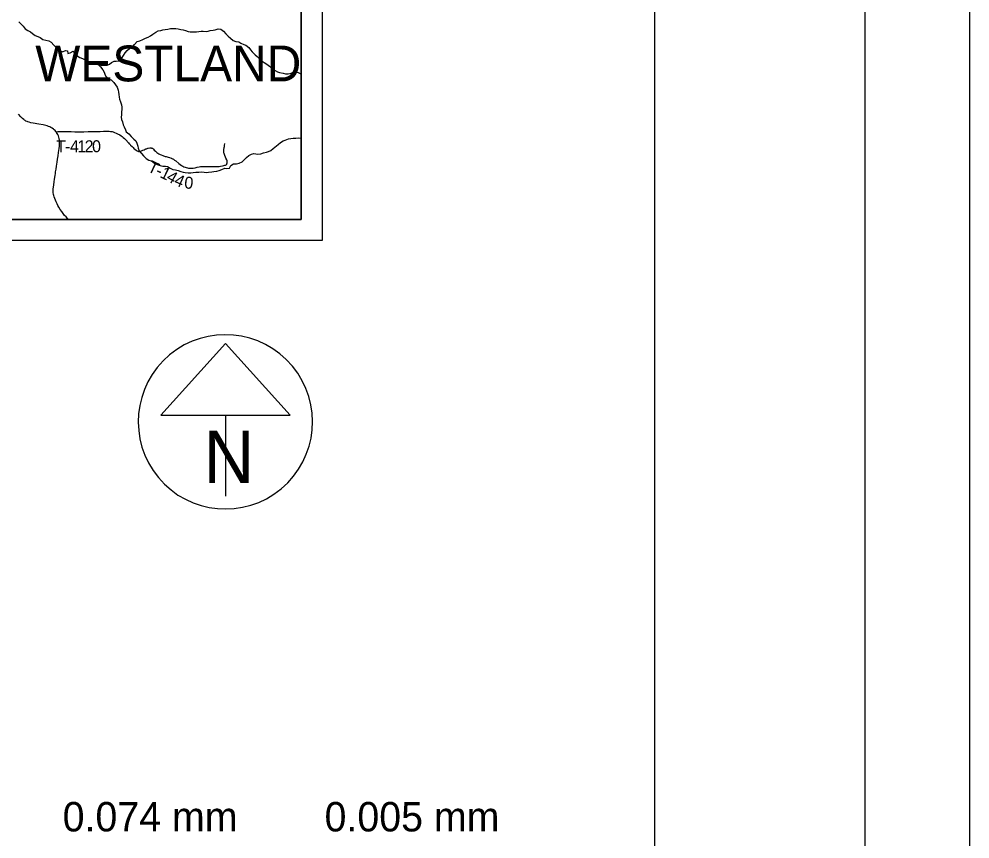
# Model space of a CAD drawing. Extents: x 0 to 34, y 0 to 22.
# Drawn here: x 29.474 to 34, y 11.151 to 15.055 of the extents above; entities that cross this region are included whole.
import ezdxf

# ---------------------------------------------------------------- set-up
doc = ezdxf.new("R2010")
doc.units = 0
for name, color, linetype in [('GM_X_Adjacent_County', 7, 'Continuous'), ('GM_X_County', 7, 'Continuous'), ('GM_X_Minor_River', 7, 'Continuous'), ('GM_X_State_Route', 7, 'Continuous'), ('GM_X_Township', 7, 'Continuous'), ('GM_X_Township_Road', 7, 'Continuous'), ('GM_X_Township_Road_Text', 7, 'Continuous'), ('GM_X_Township_Text', 7, 'Continuous'), ('SH_Border', 7, 'Continuous'), ('SH_Cut_Line', 7, 'Continuous'), ('SH_Data', 7, 'Continuous'), ('SH_Text', 7, 'Continuous')]:
    doc.layers.add(name, color=color, linetype=linetype)

msp = doc.modelspace()

# ---------------------------------------------------------------- linework, layer by layer
at = {"layer": 'GM_X_Adjacent_County'}
msp.add_lwpolyline([(28.5181, 14.1), (30.8167, 14.1), (30.8167, 20.9), (28.7526, 20.9)], dxfattribs=at)
at = {"layer": 'GM_X_County'}
msp.add_lwpolyline([(28.5181, 14.1), (30.8167, 14.1), (30.8167, 20.9), (28.7526, 20.9)], dxfattribs=at)
at = {"layer": 'GM_X_Minor_River'}
for points in [[(29.4735, 15.042), (29.4827, 15.0322), (29.4934, 15.0205), (29.5022, 15.0076), (29.5163, 14.9994), (29.5285, 14.9934), (29.5384, 14.9851), (29.5498, 14.976), (29.5631, 14.9708), (29.5749, 14.9667), (29.5871, 14.9573), (29.6008, 14.954), (29.6148, 14.9507), (29.6274, 14.9439), (29.64, 14.9303), (29.6518, 14.9175), (29.6656, 14.9055), (29.6804, 14.8984), (29.6944, 14.9049), (29.7043, 14.9031), (29.7055, 14.8902), (29.7176, 14.8937), (29.7312, 14.9017), (29.7422, 14.8916), (29.7499, 14.8798), (29.7632, 14.872), (29.7758, 14.8675), (29.791, 14.8596), (29.802, 14.854), (29.8146, 14.848), (29.8271, 14.8439), (29.837, 14.8417), (29.8503, 14.8388), (29.861, 14.8267), (29.8728, 14.8135), (29.8797, 14.8018), (29.8828, 14.7915), (29.8871, 14.7806), (29.897, 14.77), (29.913, 14.7648), (29.9248, 14.752), (29.9329, 14.741), (29.9401, 14.7308), (29.9455, 14.7164), (29.9475, 14.7069), (29.9487, 14.6956), (29.9499, 14.683), (29.9515, 14.6736), (29.9565, 14.6603), (29.9616, 14.6467), (29.9632, 14.6357), (29.9632, 14.625), (29.9622, 14.6114), (29.9608, 14.5992), (29.9605, 14.5871), (29.9621, 14.5768), (29.9659, 14.5647), (29.9694, 14.551), (29.9744, 14.5412), (29.9798, 14.528), (29.9844, 14.5181), (29.9963, 14.5076), (30.007, 14.4951), (30.0203, 14.483), (30.0302, 14.4744), (30.0352, 14.4642), (30.0395, 14.4501), (30.0403, 14.4395), (30.0457, 14.4274), (30.0568, 14.4153), (30.0664, 14.4029), (30.0794, 14.3912), (30.0923, 14.3833), (30.1045, 14.3792), (30.1182, 14.3691), (30.1311, 14.3615), (30.1448, 14.3567), (30.1589, 14.3545), (30.1714, 14.355), (30.1809, 14.352), (30.1938, 14.3445), (30.2052, 14.3389), (30.2189, 14.3375), (30.2318, 14.333), (30.2443, 14.3285), (30.255, 14.3256), (30.2645, 14.3249), (30.2781, 14.3231), (30.291, 14.3228), (30.3031, 14.3244)], [(29.8448, 14.84), (29.8514, 14.8361), (29.8636, 14.8354), (29.8738, 14.8355), (29.8837, 14.8344), (29.8935, 14.8345), (29.9037, 14.8399), (29.9135, 14.8476), (29.9268, 14.8545), (29.9366, 14.8542), (29.9487, 14.8561), (29.9608, 14.8672), (29.9702, 14.881), (29.9796, 14.8939), (29.9878, 14.9042), (30.001, 14.9153), (30.0154, 14.9246), (30.024, 14.9341), (30.0357, 14.9471), (30.0489, 14.951), (30.0622, 14.9575), (30.0754, 14.9637), (30.089, 14.9691), (30.0996, 14.9741), (30.1109, 14.9825), (30.1241, 14.9914), (30.1362, 14.9983), (30.1479, 15.0006), (30.1582, 15.0026), (30.1688, 15.005), (30.1813, 15.0069), (30.1945, 15.0089), (30.2074, 15.0094), (30.2199, 15.0102), (30.2305, 15.008), (30.2442, 15.0051), (30.2556, 15.0025), (30.2666, 14.9999), (30.278, 14.9951), (30.2879, 14.994), (30.2989, 14.9937), (30.3091, 14.9934), (30.319, 14.9938), (30.3296, 14.9954), (30.3402, 14.9974), (30.3497, 14.9967), (30.3637, 14.9961), (30.3739, 14.9976), (30.3838, 14.9996), (30.3974, 15.002), (30.4072, 15.004), (30.4216, 15.0082), (30.4345, 15.0072), (30.4467, 14.997), (30.4578, 14.9838), (30.4696, 14.9725), (30.4796, 14.9642), (30.4925, 14.9522), (30.5062, 14.9481), (30.5195, 14.9455), (30.5294, 14.9399), (30.5431, 14.9331), (30.5526, 14.9298), (30.5671, 14.9185), (30.5759, 14.9087), (30.5839, 14.8981), (30.5973, 14.8845), (30.6072, 14.877), (30.6182, 14.865), (30.6305, 14.8536), (30.6404, 14.8473), (30.6537, 14.8398), (30.6663, 14.8311), (30.6792, 14.8183), (30.6922, 14.8104), (30.7032, 14.8033), (30.7142, 14.7996), (30.7306, 14.7963), (30.7423, 14.7933), (30.7552, 14.7934), (30.7685, 14.7977), (30.7817, 14.8027), (30.7919, 14.8031), (30.8018, 14.7998), (30.8117, 14.7953), (30.8167, 14.7967)], [(30.3031, 14.3244), (30.3149, 14.3256), (30.3289, 14.3257), (30.3418, 14.3265), (30.3551, 14.3255), (30.3653, 14.3241), (30.3755, 14.326), (30.3907, 14.3265), (30.4006, 14.3281), (30.4153, 14.3308), (30.4259, 14.3332), (30.4388, 14.3386), (30.4528, 14.3444), (30.4626, 14.3426), (30.4759, 14.3453), (30.4826, 14.3571), (30.4947, 14.3648), (30.5083, 14.3657), (30.5212, 14.368), (30.536, 14.375), (30.5458, 14.3838), (30.5563, 14.3952), (30.568, 14.4044), (30.5804, 14.4117), (30.591, 14.4145), (30.6005, 14.4134), (30.6108, 14.4112), (30.624, 14.4128), (30.638, 14.4171), (30.6509, 14.421), (30.6619, 14.4244), (30.6728, 14.4295), (30.6826, 14.4383), (30.7064, 14.457), (30.7181, 14.4674), (30.7305, 14.4754), (30.7407, 14.4778), (30.7562, 14.4836), (30.7668, 14.4855), (30.779, 14.4871), (30.7911, 14.4876), (30.804, 14.4896), (30.8167, 14.4878)]]:
    msp.add_lwpolyline(points, dxfattribs=at)
at = {"layer": 'GM_X_State_Route'}
msp.add_lwpolyline([(29.7095, 14.1), (29.7046, 14.1046), (29.6973, 14.1123), (29.6908, 14.1198), (29.6839, 14.1286), (29.6774, 14.1377), (29.6702, 14.1486), (29.6639, 14.1587), (29.6589, 14.1673), (29.6548, 14.175), (29.6502, 14.1845), (29.6465, 14.1931), (29.6436, 14.2006), (29.641, 14.2083), (29.6392, 14.215), (29.6381, 14.2199), (29.6369, 14.2286), (29.6366, 14.2373), (29.6368, 14.2461), (29.6375, 14.2548), (29.6388, 14.2653), (29.6409, 14.2794), (29.6429, 14.2917), (29.6455, 14.3095), (29.6468, 14.3187), (29.648, 14.3267), (29.65, 14.3396), (29.6523, 14.3549), (29.6551, 14.3739), (29.6571, 14.3874), (29.6595, 14.404), (29.6618, 14.4194), (29.6648, 14.4384), (29.6661, 14.4488), (29.6668, 14.4575), (29.6669, 14.4661), (29.6665, 14.4735), (29.6659, 14.4784), (29.6646, 14.4856), (29.6628, 14.4921), (29.6609, 14.4979), (29.658, 14.5047), (29.6552, 14.5102), (29.6523, 14.5149), (29.6507, 14.5172), (29.6491, 14.5194), (29.6455, 14.5235), (29.6415, 14.5272), (29.6372, 14.5307), (29.6316, 14.5345), (29.6258, 14.538), (29.6197, 14.5411), (29.6135, 14.5437), (29.6077, 14.5457), (29.6012, 14.5475), (29.5891, 14.5503), (29.5677, 14.5543), (29.5402, 14.5591), (29.5298, 14.5612), (29.5219, 14.5632), (29.5153, 14.5653), (29.5118, 14.5667), (29.5068, 14.569), (29.5026, 14.5715), (29.4993, 14.574), (29.4959, 14.5767), (29.4908, 14.5813), (29.4825, 14.5897), (29.471, 14.6019)], dxfattribs=at)
at = {"layer": 'GM_X_Township'}
msp.add_lwpolyline([(28.5181, 14.1), (30.8167, 14.1), (30.8167, 18.1651)], dxfattribs=at)
at = {"layer": 'GM_X_Township_Road'}
for points in [[(29.6507, 14.5172), (29.6591, 14.5186), (29.666, 14.5194), (29.6757, 14.5199), (29.6965, 14.5197), (29.7119, 14.5192), (29.7217, 14.5188), (29.7389, 14.5179), (29.7543, 14.5175), (29.7704, 14.5175), (29.7821, 14.5179), (29.8031, 14.5187), (29.8341, 14.5195), (29.8478, 14.5196), (29.8596, 14.5196), (29.8757, 14.5201), (29.8894, 14.5203), (29.9024, 14.5202), (29.9086, 14.5198), (29.9136, 14.5192), (29.9172, 14.5185), (29.922, 14.5173), (29.9285, 14.515), (29.9359, 14.5119), (29.9426, 14.5086), (29.9528, 14.5028), (29.9591, 14.4989), (29.9649, 14.4947), (29.9699, 14.4907), (29.975, 14.4862), (29.9772, 14.4841), (29.9819, 14.4792), (29.9952, 14.4647), (29.9985, 14.4611), (30.0011, 14.4584), (30.0023, 14.4571), (30.0044, 14.4548), (30.0118, 14.4473), (30.0167, 14.4426), (30.0209, 14.4389), (30.0252, 14.4353), (30.0306, 14.4312), (30.0358, 14.4278), (30.0385, 14.4262), (30.0406, 14.4252), (30.0417, 14.4248), (30.0435, 14.4244), (30.0453, 14.4242), (30.0479, 14.424), (30.0508, 14.4245), (30.0527, 14.4251), (30.0561, 14.4266), (30.0605, 14.4288), (30.0628, 14.4298), (30.0693, 14.4328), (30.0735, 14.4347), (30.0767, 14.4361), (30.0802, 14.4373), (30.0843, 14.4386), (30.0874, 14.4394)], [(30.0874, 14.4394), (30.0891, 14.4398), (30.0957, 14.4411), (30.0988, 14.4413), (30.1019, 14.4412), (30.1049, 14.4406), (30.1083, 14.4392), (30.1114, 14.4372), (30.1142, 14.4347), (30.1176, 14.4311), (30.1232, 14.4252), (30.1267, 14.4218), (30.1296, 14.4193), (30.1341, 14.4161), (30.1394, 14.4129), (30.1449, 14.41), (30.1506, 14.4076), (30.158, 14.4048), (30.1697, 14.401), (30.1745, 14.3995), (30.1834, 14.3969), (30.1905, 14.3948), (30.1976, 14.3925), (30.1993, 14.392), (30.2008, 14.3915), (30.2041, 14.3899), (30.2063, 14.3887), (30.2089, 14.3872), (30.214, 14.3836), (30.2198, 14.379), (30.2344, 14.3674), (30.2409, 14.3626), (30.2476, 14.358), (30.2534, 14.3545), (30.2589, 14.3516), (30.2646, 14.3492), (30.2698, 14.3474), (30.2757, 14.3456), (30.2805, 14.3446), (30.2854, 14.344), (30.2903, 14.344), (30.2958, 14.3443), (30.3025, 14.3453), (30.3115, 14.3471), (30.3216, 14.3494), (30.3305, 14.3514), (30.3374, 14.3524), (30.3471, 14.3532), (30.3581, 14.3534), (30.3718, 14.3531), (30.3814, 14.3529), (30.4069, 14.352), (30.4137, 14.352), (30.4211, 14.3524), (30.4267, 14.353), (30.4329, 14.3538), (30.4414, 14.3553), (30.4481, 14.3569), (30.4528, 14.3583), (30.4562, 14.3598), (30.4589, 14.3613), (30.4609, 14.3628), (30.4621, 14.3642), (30.4634, 14.3663), (30.4644, 14.3686), (30.4649, 14.371), (30.465, 14.3734), (30.4647, 14.3759), (30.464, 14.3789), (30.4621, 14.3841), (30.4586, 14.3927), (30.4517, 14.41), (30.45, 14.4147), (30.449, 14.4183), (30.4484, 14.4225), (30.4483, 14.4268), (30.4489, 14.4323), (30.4505, 14.4426), (30.4511, 14.4474), (30.4517, 14.4528), (30.4533, 14.4621)]]:
    msp.add_lwpolyline(points, dxfattribs=at)
at = {"layer": 'SH_Border'}
msp.add_line((32.5, 0.5), (32.5, 21.5), dxfattribs=at)
msp.add_lwpolyline([(2, 21.5), (33.5, 21.5), (33.5, 0.5), (2, 0.5)], close=True, dxfattribs=at)
at = {"layer": 'SH_Cut_Line'}
msp.add_lwpolyline([(0, 0), (34, 0), (34, 22), (0, 22)], close=True, dxfattribs=at)
at = {"layer": 'SH_Data'}
for p, q in [((30.4559, 13.5108), (30.1483, 13.1696)), ((30.7635, 13.1696), (30.4559, 13.5108)), ((30.1483, 13.1696), (30.7635, 13.1696)), ((30.4559, 13.1696), (30.4559, 12.7828))]:
    msp.add_line(p, q, dxfattribs=at)
for points in [[(23.9167, 21), (30.9167, 21), (30.9167, 14), (23.9167, 14)], [(24.0167, 20.9), (30.8167, 20.9), (30.8167, 14.1), (24.0167, 14.1)]]:
    msp.add_lwpolyline(points, close=True, dxfattribs=at)
msp.add_arc((30.4559, 13.1371), 0.4148, 129.7798, 129.7633, dxfattribs=at)

# ---------------------------------------------------------------- texts
at = {"layer": 'GM_X_Township_Road_Text'}
for s, rotation, p in [('T', 0.2486, (29.6506, 14.4198)), ('-', 0.2459, (29.6931, 14.4199)), ('4', 0.2524, (29.7164, 14.42)), ('1', 0.2767, (29.7514, 14.4202)), ('2', 0.3725, (29.7865, 14.4204)), ('0', 0.6388, (29.8218, 14.4206)), ('T', 334.2917, (30.081, 14.332)), ('-', 334.217, (30.1193, 14.3136)), ('1', 333.8329, (30.1402, 14.3035)), ('4', 329.872, (30.1707, 14.2885)), ('4', 336.7164, (30.2076, 14.2676)), ('0', 354.6732, (30.2585, 14.249))]:
    msp.add_text(s, height=0.0568, rotation=rotation, dxfattribs=at).set_placement(p)
at = {"layer": 'GM_X_Township_Text'}
msp.add_text('WESTLAND', height=0.17045, rotation=0, dxfattribs=at).set_placement((29.5508, 14.7579))
at = {"layer": 'SH_Data'}
msp.add_text('N', height=0.25, dxfattribs=at).set_placement((30.3518, 12.8457))
at = {"layer": 'SH_Text'}
for s, p in [('0.074 mm', (29.6813, 11.1873)), ('0.005 mm', (30.928, 11.1873))]:
    msp.add_text(s, height=0.14, dxfattribs=at).set_placement(p)

doc.saveas('drawing.dxf')
